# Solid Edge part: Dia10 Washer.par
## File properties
Title: Dia10 Washer
Author: Dan
Template: Normal.par
Last saved by: Dan
Revision: 8
Application: Solid Edge
Material: steel
Density: 0 kg/mm^3
Accuracy: 0.99
Document Number: P52-016
Project Name: Piston Pump P52
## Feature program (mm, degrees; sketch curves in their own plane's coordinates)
sketch for "unnamed Protrusion 1" #1 plane through (0, 0, 0) normal (0, 0, 1) x-axis (1, 0, 0)
  circle centre (0, 0) radius 8
sketch for "unnamed Protrusion 1" #2 plane through (0, 0, 0) normal (0, 0, 1) x-axis (1, 0, 0)
  circle centre (0, 0) radius 5.25
extrude "unnamed Protrusion 1" add finite 1 along +normal
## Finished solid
Body 1: solid body, 4 faces, 4 edges, 0 vertices.
  Faces by surface: cylinder 2, plane 2
  Edges by curve: circle 4
Bounding box of the edges (mm): 16.000 x 16.000 x 1.000, from (-8, -8, 0) to (8, 8, 1).
Cylindrical faces by radius (mm): R5.25 x1, R8 x1
Planar faces by outward normal: +z 1, -z 1
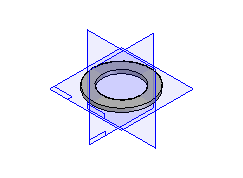
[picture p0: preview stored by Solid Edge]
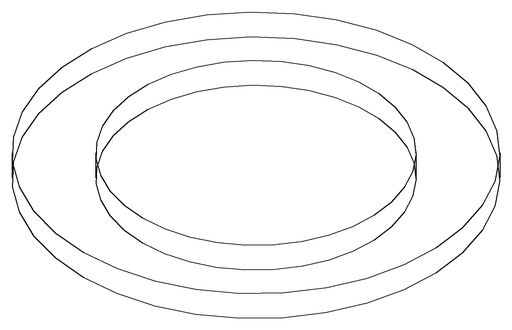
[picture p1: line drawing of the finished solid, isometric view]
